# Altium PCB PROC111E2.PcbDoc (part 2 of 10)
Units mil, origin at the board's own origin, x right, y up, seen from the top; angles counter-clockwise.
Board outline 7700 x 2300 mil, 6 copper layers (Top Layer, GND 1, SIG 1, SIG 2, GND 2, Bottom Layer), stack 78.711 mil thick; 767 components, 596 nets, 2755 pads, 1578 vias.
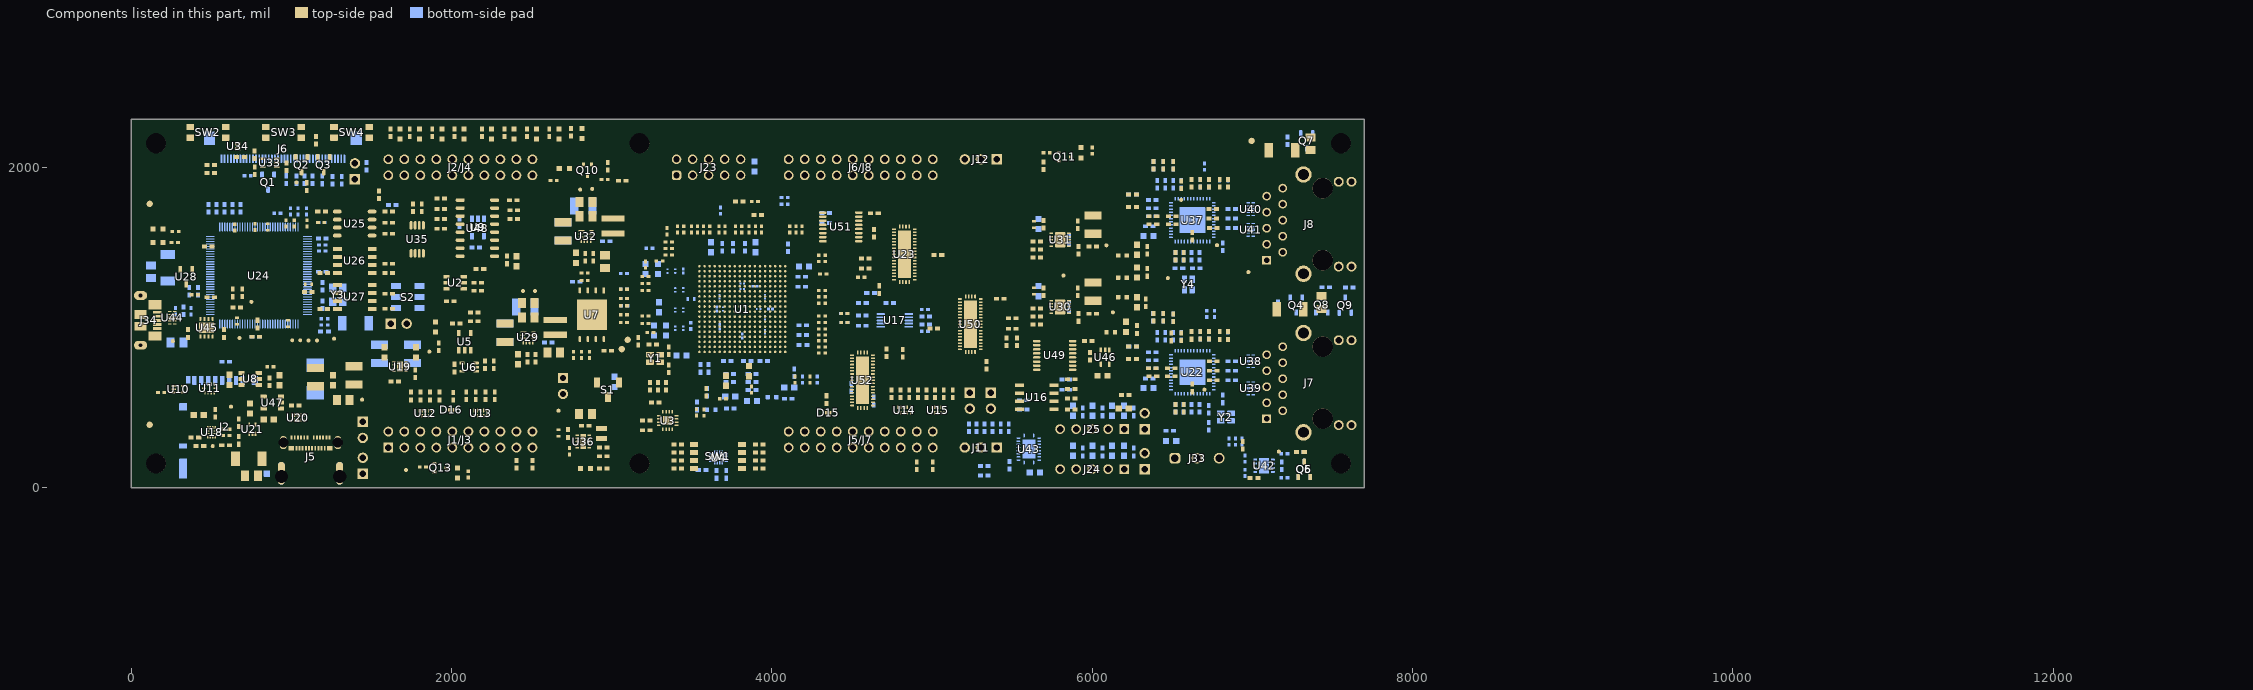
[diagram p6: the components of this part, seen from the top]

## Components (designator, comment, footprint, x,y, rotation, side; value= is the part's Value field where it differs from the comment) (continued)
R129 "ERJ-2GE0R00X" 0402 480.5,1744.01 r270 bottom value=0
R130 "ERJ-2GE0R00X" 0402L 1205.5,1054.21 r180 bottom value=0
R131 "ERJ-2GE0R00X" 0402 530.5,1744.01 r270 bottom value=0
R132 "ERJ-2GEJ101X" 0402L 1205.5,1014.22 r0 bottom value=100
R133 "CRCW040233R2FKED" 0402 580.5,1744.01 r270 bottom value=33.2
R134 "CRCW040233R2FKED" 0402 630.5,1744.01 r270 bottom value=33.2
R135 "CRCW040233R2FKED" 0402 680.5,1744.01 r270 bottom value=33.2
R136 "CRCW0402330KFKED" 0402L 275.17,1101.38 r90 bottom value=330k
R137 "CRCW0402330KFKED" 0402L 371.47,1101.38 r270 bottom value=330k
R138 "CRCW04021K00FKED" 0402L 1187.62,1656.39 r0 bottom value=1.00k
R139 "CRCW04021K00FKED" 0402L 1093.35,1724.68 r90 bottom value=1.00k
R140 "CRCW04021K00FKED" 0402L 1039.13,1724.68 r90 bottom value=1.00k
R141 "CRCW04021K00FKED" 0402L 992.24,1724.68 r90 bottom value=1.00k
R142 "CRCW040249R9FKED" 0402L 1191.36,1514.93 r0 bottom value=49.9
R143 "CRCW040210K0FKED" 0402L 1191.36,1476.93 r0 bottom value=10.0k
R144 "CRCW04021K00FKED" 0402L 395.32,1204.12 r180 top value=1.00k
R145 "CRCW04024K87FKED" 0402L 911.79,1713.62 r0 bottom value=4.87k
R146 "ERJ-2RKF1002X" 0402 2602.33,906.68 r0 bottom value=10.0k
R147 "ERJ-2RKF1002X" 0402 5654.13,1117.63 r180 top value=10.0k
R148 "ERJ-6ENF1822V" 0805_HV 2637.33,844.68 r180 top value=18.2k
R149 "ERJ-2GE0R00X" 0402 5654.13,1017.63 r0 top value=0
R150 "ERJ-2GE0R00X" 0402 5654.13,1067.63 r0 top value=0
R151 "CRCW04023K57FKED" 0402 6004.13,1085.98 r0 top value=3.57k
R152 "CRCW04021K69FKED" 0402 5914.13,1062.36 r90 top value=1.69k
R153 "CRCW04022K49FKED" 0402 2522.33,806.68 r270 top value=2.49k
R154 "CRCW04024K99FKED" 0402 2472.33,806.68 r90 top value=4.99k
R155 "ERJ-2RKF1002X" 0402 5654.13,1536.82 r180 top value=10.0k
R156 "ERJ-2RKF1002X" 0402 2965.12,1537.88 r0 bottom value=10.0k
R157 "ERJ-2GE0R00X" 0402 5654.13,1436.82 r0 top value=0
R158 "ERJ-2GE0R00X" 0402 5654.13,1486.82 r0 top value=0
R159 "CRCW04021K87FKED" 0402 6004.13,1505.17 r0 top value=1.87k
R160 "ERJ-6ENF1822V" 0805_HV 2956.47,1410.85 r90 top value=18.2k
R161 "CRCW04024K99FKED" 0402 5914.13,1481.55 r90 top value=4.99k
R162 "CRCW040215K4FKED" 0402 2884,1439.3 r270 top value=15.4k
R163 "CRCW04024K99FKED" 0402 2834,1439.3 r90 top value=4.99k
R164 "ERJ-2GE0R00X" 0402L 3707,1612.48 r270 top value=0
R165 "ERJ-2GE0R00X" 0402L 3492.19,1009.41 r90 bottom value=0
R166 "ERJ-2GE0R00X" 0402L 3773,1612.48 r270 top value=0
R167 "ERJ-2GE0R00X" 0402L 3209.68,1024.38 r0 top value=0
R168 "ERJ-2GE0R00X" 0402L 3209.68,1072.38 r0 top value=0
R169 "ERJ-2GE0R00X" 0402L 3935,1612.48 r270 top value=0
R170 "ERJ-2GE0R00X" 0402L 3893.31,1786.65 r0 top value=0
R171 "ERJ-2GE0R00X" 0402L 3897,1612.48 r270 top value=0
R172 "ERJ-2GE0R00X" 0402L 3857,1612.48 r270 top value=0
R173 "ERJ-2RKF1002X" 0402 3910.59,1702.62 r180 top value=10.0k
R174 "ERJ-2RKF1002X" 0402 3795.44,1786.65 r180 top value=10.0k
R175 "CRCW04024K70JNED" 0402 4903.31,136.03 r270 top value=4.7k
R176 "CRCW04024K70JNED" 0402 5004.17,136.03 r270 top value=4.7k
R177 "ERJ-2RKF1002X" 0402 966.87,1923.62 r270 bottom value=10.0k
R178 "ERJ-2RKF1002X" 0402 968.08,2004.52 r270 top value=10.0k
R179 "ERJ-2RKF1002X" 0402 769.09,2077.36 r90 top value=10.0k
R180 "ERJ-2GE0R00X" 0402L 725.69,1947.32 r180 bottom value=0
R181 "ERJ-2RKF1002X" 0402 1151.5,2170 r90 top value=10.0k
R182 "ERJ-2RKF1002X" 0402 1255,1920 r90 bottom value=10.0k
R183 "ERJ-2RKF1002X" 0402 1627.39,1765 r180 bottom value=10.0k
R184 "ERJ-2RKF1002X" 0402 1094.86,1880 r90 top value=10.0k
R185 "ERJ-2RKF1002X" 0402 1190.9,1920.91 r90 bottom value=10.0k
R186 "ERJ-2RKF1002X" 0402 1129.84,1921.38 r90 bottom value=10.0k
R187 "ERJ-2RKF1002X" 0402 1079.84,1921.38 r90 bottom value=10.0k
R188 "ERJ-2RKF1002X" 0402 1029.84,1921.38 r90 bottom value=10.0k
R189 "CRCW04024K70JNED" 0402 1468,2007 r90 bottom value=4.7k
R190 "CRCW04024K70JNED" 0402 1813.28,1748.34 r90 top value=4.7k
R191 "CRCW04024K70JNED" 0402 1312.52,1920 r270 bottom value=4.7k
R192 "CRCW04024K70JNED" 0402 1758.28,1748.34 r90 top value=4.7k
R193 "ERJ-2GE0R00X" 0402L 2735,226.63 r270 top value=0
R194 "ERJ-2RKF1002X" 0402 2945,250.25 r0 top value=10.0k
R195 "ERJ-2RKF1003X" 0402 2945,195.25 r0 top value=100k
R196 "ERJ-2GE0R00X" 0402 6375.51,1695.04 r0 bottom value=0
R197 "ERJ-2GE0R00X" 0402 6506.28,1895 r270 bottom value=0
R198 "ERJ-2GE0R00X" 0402 6375.51,1745.04 r0 bottom value=0
R199 "ERJ-2GE0R00X" 0402 6375.51,1795.04 r0 bottom value=0
R200 "ERJ-2GE0R00X" 0402 6406.28,1895 r270 bottom value=0
R201 "ERJ-2GE0R00X" 0402 6456.28,1895 r270 bottom value=0
R202 "ERJ-2RKF1152X" 0402 6815,1503.37 r90 bottom value=11.5k
R203 "CRCW04022K49FKED" 0402 6251.38,1752.65 r180 top value=2.49k
R204 "CRCW04022K49FKED" 0402 6251.38,1830.96 r180 top value=2.49k
R205 "CRCW04022K49FKED" 0402 6506.28,2013.05 r90 top value=2.49k
R206 "CRCW04022K49FKED" 0402 6796.28,1899.68 r90 top value=2.49k
R207 "CRCW04022K49FKED" 0402 6674.39,1900.08 r90 top value=2.49k
R208 "CRCW04022K49FKED" 0402 6729.39,1900.08 r90 top value=2.49k
R209 "CRCW04022K49FKED" 0402 6520,1445 r270 top value=2.49k
R210 "CRCW04022K49FKED" 0402 6383.01,2012.97 r90 top value=2.49k
R211 "CRCW04022K49FKED" 0402 6443.01,2012.97 r90 top value=2.49k
R212 "ERJ-2GE0R00X" 0402 6570,1445 r90 bottom value=0
R213 "ERJ-2GE0R00X" 0402 6520,1445 r90 bottom value=0
R214 "ERJ-2GE0R00X" 0402 6620,1445 r90 bottom value=0
R215 "CRCW04022K49FKED" 0402 6251.3,1752.65 r0 bottom value=2.49k
R216 "CRCW04022K49FKED" 0402 6251.38,1830.96 r0 bottom value=2.49k
R217 "CRCW04022K49FKED" 0402 6506.28,2013.05 r270 bottom value=2.49k
R218 "CRCW04022K49FKED" 0402 6848,1899.68 r270 top value=2.49k
R219 "CRCW04022K49FKED" 0402 6674.39,1900.08 r270 bottom value=2.49k
R220 "CRCW04022K49FKED" 0402 6729.39,1900.08 r270 bottom value=2.49k
R221 "CRCW04022K49FKED" 0402 6570.97,1444.88 r90 top value=2.49k
R222 "CRCW04022K49FKED" 0402 6383.01,2012.97 r270 bottom value=2.49k
R223 "CRCW04022K49FKED" 0402 6443.01,2012.97 r270 bottom value=2.49k
R224 "CRCW0402220RJNED" 0402 7160.2,1135 r270 bottom value=220
R225 "ERJ-2GE0R00X" 0402L 6715,1084.62 r270 bottom value=0
R226 "CRCW0402220RJNED" 0402 7300.38,221.46 r180 top value=220
R227 "ERJ-2GE0R00X" 0402L 6762.73,1085 r270 bottom value=0
R228 "CRCW0402220RJNED" 0402 7300.38,221.46 r180 bottom value=220
R229 "ERJ-2GE0R00X" 0402L 6846.59,947.67 r270 bottom value=0
R230 "CRCW0402220RJNED" 0402 7220,2165 r270 bottom value=220
R231 "ERJ-2GE0R00X" 0402L 6700,2004.69 r270 bottom value=0
R232 "CRCW0402220RJNED" 0402 7457.49,1251.28 r0 bottom value=220
R233 "ERJ-2GE0R00X" 0402L 6795,1896.38 r270 bottom value=0
R234 "CRCW0402220RJNED" 0402 7603.95,1250 r0 bottom value=220
R235 "ERJ-2GE0R00X" 0402L 6848,1896.38 r270 bottom value=0
R236 "ERJ-2RKF4992X" 0402 6259.18,222.12 r90 bottom value=49.9k
R237 "ERJ-2RKF4992X" 0402 6064.18,222.13 r90 bottom value=49.9k
R238 "ERJ-2RKF4992X" 0402 5940,222.13 r90 bottom value=49.9k
R239 "ERJ-2RKF4992X" 0402 6259.18,472.12 r90 bottom value=49.9k
R240 "ERJ-2RKF4992X" 0402 6064.18,472.13 r90 bottom value=49.9k
R241 "ERJ-2RKF4992X" 0402 5940,472.13 r90 bottom value=49.9k
R242 "ERJ-2RKF4992X" 0402 6485.13,355.53 r0 bottom value=49.9k
R243 "ERJ-2RKF4992X" 0402 6205,578.2 r180 top value=49.9k
R244 "CRCW040210K0FKED" 0402L 6935,287.55 r90 bottom value=10.0k
R245 "ERJ-2GE0R00X" 0402L 7200,211.46 r180 bottom value=0
R246 "CRCW040261R9FKED" 0402L 6952.8,91.77 r90 bottom value=61.9
R247 "CRCW040261R9FKED" 0402L 6952.8,181.14 r270 bottom value=61.9
R248 "ERJ-2GE0R00X" 0402L 6855,287.55 r90 bottom value=0
R249 "ERJ-2GE0R00X" 0402L 7200,61.46 r180 bottom value=0
R250 "CRCW040210K0FKED" 0402L 6895,287.55 r270 bottom value=10.0k
R251 "CRCW040251K1FKED" 0402 631.97,1215.23 r90 top value=51.1k
R252 "CRCW040230K0FKED" 0402 691.97,1217.17 r270 top value=30.0k
R253 "ERJ-6ENF1004V" 0805_HV 122.89,1348.06 r90 bottom value=1.00Meg
R254 "ERJ-6ENF1004V" 0805_HV 7430.57,1155 r90 top value=1.00Meg
R255 "ERJ-6ENF1004V" 0805_HV 7364.16,2146.97 r90 top value=1.00Meg
R256 "ERJ-2GEJ102X" 0402 4816.77,838.02 r90 top value=1.0k
R257 "ERJ-2RKF5100X" 0402 1918.27,879.01 r270 top value=510
R258 "ERJ-2RKF1002X" 0402 2974.53,2005.57 r90 top value=10.0k
R259 "ERJ-2GEJ361X" 0402L 270,1530 r0 top value=360
R260 "ERJ-2GEJ361X" 0402L 275,1600 r0 top value=360
R261 "CRCW04021K00FKED" 0402L 965,1650 r270 top value=1.00k
R262 "ERJ-2RKF2200X" 0402 2609.29,2216.18 r270 top value=220
R263 "ERJ-2RKF2200X" 0402 2469.29,2216.18 r270 top value=220
R264 "ERJ-2RKF2200X" 0402 2329.29,2216.18 r270 top value=220
R265 "ERJ-2GEJ361X" 0402L 2636.09,1917.12 r180 top value=360
R266 "ERJ-2RKF2200X" 0402 2189.29,2216.18 r270 top value=220
R267 "ERJ-2RKF2200X" 0402 2017.87,2216.18 r270 top value=220
R268 "ERJ-2RKF1002X" 0402 3065,1915.46 r0 top value=10.0k
R269 "ERJ-2RKF1002X" 0402 2388.01,1731.55 r180 top value=10.0k
R270 "ERJ-2RKF1002X" 0402 1930.93,1676.88 r0 top value=10.0k
R271 "ERJ-2RKF1002X" 0402 1930.93,1804.54 r0 top value=10.0k
R272 "ERJ-2GEJ511X" 0402L 2955,1923.35 r180 top value=510
R273 "ERJ-2RKF2200X" 0402 1877.87,2216.18 r270 top value=220
R274 "ERJ-2RKF1002X" 0402 1930.93,1739.85 r0 top value=10.0k
R275 "ERJ-2RKF1002X" 0402 2388.01,1676.55 r180 top value=10.0k
R276 "ERJ-2RKF1002X" 0402 1930.93,1616.57 r0 top value=10.0k
R277 "ERJ-2RKF2200X" 0402 1737.87,2216.18 r270 top value=220
R278 "ERJ-2GEJ102X" 0402 2385,1795 r180 top value=1.0k
R279 "ERJ-2RKF2200X" 0402 1617.87,2216.18 r270 top value=220
R280 "ERJ-2GE0R00X" 0402L 3074.77,1031.94 r0 top value=0
R281 "ERJ-2GE0R00X" 0402L 3075,1239.6 r0 bottom value=0
R282 "ERJ-2GE0R00X" 0402L 4143,674.68 r90 top value=0
R283 "ERJ-2GE0R00X" 0402L 4190,674.68 r90 bottom value=0
R284 "ERJ-2GE0R00X" 0402L 4282.93,674.68 r90 bottom value=0
R285 "ERJ-2GE0R00X" 0402L 4236.47,674.68 r90 top value=0
R286 "ERJ-2GE0R00X" 0402L 4312.25,1231.79 r180 top value=0
R287 "ERJ-2RKF1002X" 0402 5530,911.55 r90 top value=10.0k
R288 "ERJ-2RKF1002X" 0402 4581.73,1430.9 r0 top value=10.0k
R289 "ERJ-2GEJ102X" 0402 5465.31,911.55 r90 top value=1.0k
R290 "ERJ-2GEJ102X" 0402 4581.73,1367.93 r0 top value=1.0k
R291 "ERJ-2RKF1002X" 0402 4565,1152.36 r0 bottom value=10.0k
R292 "ERJ-2RKF1002X" 0402 5501.38,1057.02 r180 top value=10.0k
R293 "ERJ-2GEJ102X" 0402 4615.26,1215.33 r180 bottom value=1.0k
R294 "ERJ-2GEJ102X" 0402 5501.38,992.02 r180 top value=1.0k
R295 "ERJ-2RKF1002X" 0402 1990,1163.59 r0 top value=10.0k
R296 "ERJ-2RKF1002X" 0402 2176.41,1365 r0 top value=10.0k
R297 "ERJ-2GE0R00X" 0402L 3811,1612.92 r270 top value=0
R298 "ERJ-2RKF1002X" 0402 4336.51,1715.49 r180 bottom value=10.0k
R299 "ERJ-2RKF1002X" 0402 1023.5,512.5 r0 top value=10.0k
R300 "ERJ-2GEJ102X" 0402 4336.51,1652.52 r180 bottom value=1.0k
R302 "ERJ-2GEJ361X" 0402L 6000,2104.27 r270 top value=360
R303 "ERJ-2GEJ511X" 0402L 5715,2090.86 r0 top value=510
R304 "ERJ-2GEJ102X" 0402 5695.31,2008.64 r90 top value=1.0k
R305 "ERJ-2RKF1002X" 0402 6620,950 r270 top value=10.0k
R306 "ERJ-2RKF1002X" 0402 6620,1900.08 r270 top value=10.0k
R307 "ERJ-2GE0R00X" 0402L 3693.94,555 r0 top value=0
R308 "CRCW04021K00FKED" 0402L 1016.99,1650 r270 top value=1.00k
R309 "CRCW04021K00FKED" 0402L 1095.89,1650 r270 top value=1.00k
R310 "CRCW04021K00FKED" 0402L 1184.6,1656.39 r0 top value=1.00k
R311 "CRCW04021K00FKED" 0402L 645,1625 r270 top value=1.00k
R312 "CRCW04021K00FKED" 0402L 772.07,1627.63 r270 top value=1.00k
R313 "CRCW0402130RFKED" 0402 2745.47,2220.12 r270 top value=130
R314 "ERJ-2GEJ361X" 0402L 2103.52,81.9 r90 top value=360
R315 "CRCW0402130RFKED" 0402 2945,120 r0 top value=130
R316 "ERJ-2RKF1002X" 0402 5570,545.04 r0 bottom value=10.0k
R317 "ERJ-2GEJ511X" 0402L 1819.99,127.49 r0 top value=510
R318 "ERJ-2RKF1002X" 0402 5868.93,488.21 r180 top value=10.0k
R319 "ERJ-2RKF1002X" 0402 5835.31,675 r180 bottom value=10.0k
R320 "ERJ-2RKF1002X" 0402 5868.93,676.73 r180 top value=10.0k
R321 "ERJ-2RKF1002X" 0402 5868.93,556.99 r180 top value=10.0k
R322 "ERJ-2RKF1002X" 0402 5835.31,611.02 r180 bottom value=10.0k
R323 "ERJ-2RKF1002X" 0402 5868.93,615 r180 top value=10.0k
R324 "CRCW040233R2FKED" 0402 1607.87,1653.35 r180 top value=33.2
R325 "CRCW040233R2FKED" 0402 1607.87,1584.92 r180 top value=33.2
R326 "CRCW040233R2FKED" 0402 1607.87,1398.01 r180 top value=33.2
R327 "CRCW040233R2FKED" 0402 1607.87,1210 r180 top value=33.2
R328 "CRCW040233R2FKED" 0402 5325,75 r0 bottom value=33.2
R329 "CRCW040233R2FKED" 0402 5325,135.09 r0 bottom value=33.2
R330 "CRCW040233R2FKED" 0402 5229.44,373.51 r270 bottom value=33.2
R331 "CRCW040233R2FKED" 0402 5277.45,373.51 r270 bottom value=33.2
R332 "CRCW040233R2FKED" 0402 5327.45,373.51 r270 bottom value=33.2
R333 "CRCW040233R2FKED" 0402 5377.45,373.51 r270 bottom value=33.2
R334 "CRCW040233R2FKED" 0402 5428.06,373.51 r270 bottom value=33.2
R335 "CRCW040233R2FKED" 0402 5478.01,373.51 r270 bottom value=33.2
S1 "CAS-120TA" SW_CAS-120TA 2975.61,610.94 r270 top
S2 "CAS-D20TA" SW_CAS-D20TA 1724.71,1190 r180 bottom
SH-J1 "60900213421" Wurth_60900213421 12985,2675 r90 top
SH-J2 "60900213421" Wurth_60900213421 9590,2508.18 r90 top
SH-J3 "60900213421" Wurth_60900213421 9590,2146.97 r90 top
SH-J4 "60900213421" Wurth_60900213421 1850.31,-280 r180 top
SH-J5 "60900213421" Wurth_60900213421 1875,-160 r180 top
SH-J6 "60900213421" Wurth_60900213421 4355,-120 r180 top
SH-J7 "60900213421" Wurth_60900213421 4345,-250 r180 top
SW1 "416131160804" FP-416131160804_SMT_SW-MFG 3662.3,194.51 r90 top
SW2 "434351045816" FP-434351045816_SMT_SW_4MM7_4MM5-MFG 477.56,2218.82 r180 top
SW3 "434351045816" FP-434351045816_SMT_SW_4MM7_4MM5-MFG 950,2218.82 r180 top
SW4 "434351045816" FP-434351045816_SMT_SW_4MM7_4MM5-MFG 1375,2218.82 r180 top
TP1 "TP_SM_1MM" TP_SM_1MM 3098.87,922.75 r90 top
TP2 "TP_SM_1MM" TP_SM_1MM 3061.79,864.43 r90 top
TP3 "TESTPOINT" TP_25MIL-SMT 621.55,505.45 r90 top
TP4 "TESTPOINT" TP_25MIL-SMT 1440,548.85 r180 top
TP5 "TESTPOINT" TP_25MIL-SMT 507.51,259.31 r90 top
TP6 "TESTPOINT" TP_25MIL-SMT 2666.85,480 r90 top
TP7 "TESTPOINT" TP_25MIL-SMT 6700.57,611.5 r180 top
TP8 "TESTPOINT" TP_25MIL-SMT 1860,848.96 r90 top
TP9 "TESTPOINT" TP_25MIL-SMT 2877.25,1865 r90 top
TP10 "TESTPOINT" TP_25MIL-SMT 2520,1228.07 r90 top
TP11 "TESTPOINT" TP_25MIL-SMT 6088.14,1513.04 r90 top
TP12 "TESTPOINT" TP_25MIL-SMT 6128.41,1094.72 r90 top
TP13 "TESTPOINT" TP_25MIL-SMT 1715,110 r90 top
TP14 "TESTPOINT" TP_25MIL-SMT 2802.41,1860.51 r90 top
TP15 "TESTPOINT" TP_25MIL-SMT 2445,1228.07 r90 top
TP16 "TESTPOINT" TP_25MIL-SMT 6471.65,1308.13 r90 top
TP17 "TESTPOINT" TP_25MIL-SMT 5820,1323.71 r90 top
TP18 "TESTPOINT" TP_25MIL-SMT 1030,1905 r90 top
TP19 "TESTPOINT" TP_25MIL-SMT 6779.03,1513.91 r0 top
TP20 "TESTPOINT" TP_25MIL-SMT 6555,1797.09 r270 top
TP21 "TESTPOINT" TP_25MIL-SMT 6975,1345.45 r90 top
TP22 "TESTPOINT" TP_25MIL-SMT 7165,225 r90 top
TP23 "TESTPOINT" TP_25MIL-SMT 258.56,915 r0 top
TP24 "TESTPOINT" TP_25MIL-SMT 748.48,1160.35 r0 top
TP25 "TESTPOINT" TP_25MIL-SMT 674.75,934.53 r270 top
TP26 "TESTPOINT" TP_25MIL-SMT 1265,929.89 r0 top
TP27 "TESTPOINT" TP_25MIL-SMT 1003.9,920 r270 top
TP28 "TESTPOINT" TP_25MIL-SMT 1053.9,920 r270 top
TP29 "TESTPOINT" TP_25MIL-SMT 1105.9,919 r270 top
TP30 "TESTPOINT" TP_25MIL-SMT 1158.9,919 r270 top
U1 "AM263x_0p96" "ZCZ (S-PBGA-N324)" 3547.13,1382.8 r0 top locked
U2 "SN74LVC1G11DBVR" DBV0006A_N 2021.24,1279.45 r0 top
U3 "TCA6408ARGTR" RGT0016A 3348.05,418.7 r90 top
U4 "SN74AVC4T245RSVR" RSV0016A 3666.07,187.78 r90 bottom
U5 "SN74LVC1G08DBVR" DBV0005A_N 2081.31,911.4 r90 top
U6 "SN74LVC1G17DCKR" DCK0005A_N 2108.67,752.39 r180 top
U7 "S25FL128SAGNFI000" FP-S25FL128SAGNFI000_WSON8-IPC_B 2875,1079.5 r270 top locked
U8 "TPS22918TDBVTQ1" DBV0006A_N 741.03,678.6 r180 top
U9 "SN74LVC1G08DBVR" DBV0005A_N 2163.97,1624.3 r270 bottom
U10 "TPD2E001DRLR" DRL0005A 292.78,614.21 r0 top
U11 "TPD6E001RSER" RSE0010A 488.2,620 r270 top
U12 "TPD4E02B04DQAR" DQA0010A#1 1835,464.48 r90 top
U13 "TPD4E02B04DQAR" DQA0010A#1 2180,465 r90 top
U14 "TPD4E02B04DQAR" DQA0010A#1 4825,484.12 r90 top
U15 "TPD4E02B04DQAR" DQA0010A#1 5035.4,484.26 r90 top
U16 "CAT24M01WI-GT3" SOIC-8 5652.8,564.14 r180 top
U17 "TS5A23159DGSR" DGS0010A_N 4767.68,1043.75 r0 bottom
U18 "TUSB320LIRWBR" RWB0012A 500.2,345.08 r0 top
U19 "TPS22965TDSGRQ1" DSG0008B 1676.92,755.91 r0 top
U20 "TPD4E02B04DQAR" DQA0010A#1 1038.54,436.99 r270 top
U21 "SN74AHC1G02DRLR" DRL0005A 755.3,365 r90 top
U22 "DP83869HMRGZT" RGZ0048B-MFG 6625.18,720.04 r180 bottom
U23 "TS3DDR3812RUAR" RUA0042A-MFG 4827.2,1456.5 r0 top
U24 "TM4C1294NCPDTT3" PDT0128A 795.5,1324.37 r0 bottom locked
U25 "ISO7220CDR" D0008B_N 1393.86,1648.86 r0 top
U26 "ISO7721DR" D0008B_HV 1395,1415 r180 top
U27 "ISO7721DR" D0008B_HV 1395,1190.27 r180 top
U28 "LM4040C25QDBZR" DBZ0003A_N 341.5,1316.65 r270 top
U29 "TPS62913RPUR" RPU0010A-MFG 2475.89,941.68 r180 top
U30 "TPS74801DRCR" DRC0010J 5799.13,1128.43 r0 top
U31 "TPS74801DRCR" DRC0010J 5799.13,1547.62 r0 top
U32 "TPS62913RPUR" RPU0010A-MFG 2837.56,1574.3 r180 top
U33 "SN74LVC1G07DCKT" DCK0005A_N 863.37,2028.15 r180 top
U34 "SN74LVC2G17DSF2" DSF0006A 665,2131.22 r270 top
U35 "TCA9617BDGKR" DGK0008A_N 1784.37,1550 r90 top
U36 "TPS62177DQCR" DQC0010A 2821.22,287.66 r0 top
U37 "DP83869HMRGZT" RGZ0048B-MFG 6625.18,1670.04 r180 bottom
U38 "TPD4E05U06DQAR" DQA0010A#2 6989.58,788.94 r180 bottom
U39 "TPD4E05U06DQAR" DQA0010A#2 6989.31,619.6 r180 bottom
U40 "TPD4E05U06DQAR" DQA0010A#2 6989.58,1738.94 r180 bottom
U41 "TPD4E05U06DQAR" DQA0010A#2 6989.31,1609.6 r180 bottom
U42 "TCAN1044VDRBTQ1" DRB0008J 7072.8,136.46 r180 bottom
U43 "TXB0108RGYR" RGY0020A 5603.66,240.62 r0 bottom
U44 "TPD4E02B04DQAR" DQA0010A#1 255,1060.81 r180 top
U45 "TPS79601DRBR" DRB0008B 468.69,998.32 r90 top
U46 "SN74LVC1G04DCKR" DCK0005A_N 6080,815 r270 top
U47 "SN74LVC1G08DBVR" DBV0005A_N 879.5,531 r180 top
U48 "TPIC2810D" D0016A_N 2160,1620 r180 top locked
U49 "SN74CB3Q3257PWR" PW0016A_L 5765,825.23 r0 top
U50 "TS3DDR3812RUAR" RUA0042A-MFG 5238.39,1020.04 r180 top
U51 "SN74CB3Q3257PWR" PW0016A_L 4430,1627.91 r0 top
U52 "TS3DDR3812RUAR" RUA0042A-MFG 4565,670 r180 top
Y1 "ABM10W-25.0000MHZ-4-D1X-T3" Abracon_ABM10W 3270,806.21 r90 top
Y2 "ABM10W-25.0000MHZ-4-D1X-T3" Abracon_ABM10W 6834.6,440.5 r90 bottom
Y3 "NX3225GA-16.000M-STD-CRG-1" NDK_NX3225GA 1287.13,1204.32 r180 bottom
Y4 "ABM10W-25.0000MHZ-4-D1X-T3" Abracon_ABM10W 6600,1268.41 r0 bottom
ZZ1 "This Assembly Note is for PCB labels only" AssemblyNoteLabel 100,7500 r0 top
ZZ2 "These assemblies are ESD sensitive, ESD precautions shall be observed." AssemblyNote 100,7400 r0 top
ZZ3 "These assemblies must be clean and free from flux and all contaminants. Use of no clean flux is not acceptable." AssemblyNote 100,7300 r0 top
ZZ4 "These assemblies must comply with workmanship standards IPC-A-610 Class 2, unless otherwise specified." AssemblyNote 100,7200 r0 top
? "Comment" MISTRAL_LOGO_25 6689.32,1155.04 r0 top
? "Comment" MHNP_M3_PANHEAD_PHILLIPS 3173.18,150 r0 top
? "Comment" MHNP_M3_PANHEAD_PHILLIPS 7554.17,150 r0 top
? "Comment" MHNP_M3_PANHEAD_PHILLIPS 7554.17,2150 r0 top locked
? "Comment" MHNP_M3_PANHEAD_PHILLIPS 3173.18,2150 r0 top locked
? "Comment" MHNP_M3_PANHEAD_PHILLIPS 154.17,2150 r0 top
? "Comment" MHNP_M3_PANHEAD_PHILLIPS 154.17,150 r0 top locked

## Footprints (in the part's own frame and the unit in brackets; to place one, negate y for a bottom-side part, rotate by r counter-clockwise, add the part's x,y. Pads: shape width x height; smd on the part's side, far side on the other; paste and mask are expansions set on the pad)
0201 [mm] "Data from Kemet datasheet CC101_COM dated 7/28/11"
  rect 0.46x0.42 smd mask+0.048: 1(-0.33,0) 2(0.33,0)
  body extent -0.31,-0.16 0.31,0.16, height 0.26
0402 [mm] "0402 from SM-752 data"
  rect 0.8x0.6 smd: 1(-0.6,0) 2(0.6,0)
  silkscreen extent -1.22,-0.52 1.22,0.52, body extent -0.55,-0.3 0.55,0.3, height 0.6
0402_070 [mil] "SMD, 2-Leads, Body 1.2x0.7mm, Height 0.7mm"
  rect 15x24 smd: 1(-20,0) 2(20,0)
  body extent -24,-14 24,14, height 28
0402L [mm] "0402 from SM-752 data"
  rect 0.6x0.5 smd: 1(-0.5,0) 2(0.5,0)
  body extent -0.55,-0.3 0.55,0.3, height 0.6
0402S [mil] "Based on C0402S footprint from PADS legacy"
  rect 15x24 smd: 1(-20,0) 2(20,0)
  body extent -22,-12 22,12, height 24
0603 [mm] "0603 from SM-752 data"
  rect 1x0.95 smd: 1(-0.8,0) 2(0.8,0)
  silkscreen extent -1.52,-0.69 1.52,0.69, body extent -0.87,-0.47 0.87,0.47, height 1
0805_HV [mil] "0805 with 30mil clearance between pads"
  rect 50x63 smd: 1(-40,0) 2(40,0)
  silkscreen extent -74,-40 74,40, body extent -43,-29 43,29, height 57
1210_270 [mm] "1210"
  rect 1.3x2.7 smd: 1(-1.45,0) 2(1.45,0)
  silkscreen extent -2.32,-1.57 2.32,1.57, body extent -1.7,-1.35 1.7,1.35, height 2.7
1808 [mm] "Chip Capacitor, Body 4.6x2.0mm, IPC Medium Density"
  rect 1.4x2.3 smd: 1(-2.1,0) 2(2.1,0)
  silkscreen extent -3.1,-1.45 3.1,1.45, body extent -2.47,-1.2 2.47,1.2, height 2.03
Abracon_ABM10W [mm] "SMD, 4-Leads, Body 2x2.5mm"
  rrect12% 0.85x1.2 smd: 1(-0.6,0.813) 2(-0.6,-0.813) 3(0.6,-0.813) 4(0.6,0.813)
  body extent -1.05,-1.3 1.05,1.3, height 0.6
AssemblyNote [mil] "Assembly Note"
AssemblyNoteLabel [mil] "Assembly Note for PCB Labels"
BoosterPack_40pin_J1J3 [mm] "Receptacle, 2.54mm, 10x2, TH"
  rrect6% 1.55x1.55 hole 1.02: 1(1.27,11.43)
  round 1.55 hole 1.02: 2(1.27,8.89) 3(1.27,6.35) 4(1.27,3.81) 5(1.27,1.27) 6(1.27,-1.27) 7(1.27,-3.81) 8(1.27,-6.35) 9(1.27,-8.89) 10(1.27,-11.43) 21(-1.27,11.43) 22(-1.27,8.89) 23(-1.27,6.35) 24(-1.27,3.81) 25(-1.27,1.27) 26(-1.27,-1.27) 27(-1.27,-3.81) 28(-1.27,-6.35) 29(-1.27,-8.89) 30(-1.27,-11.43)
  silkscreen extent -7.62,-12.95 7.62,12.95, body extent -2.48,-12.95 2.48,12.95, height 8.51
BoosterPack_40pin_J2J4 [mm] "Receptacle, 2.54mm, 10x2, TH"
  round 1.55 hole 1.02: 11(-1.27,-11.43) 12(-1.27,-8.89) 13(-1.27,-6.35) 14(-1.27,-3.81) 15(-1.27,-1.27) 16(-1.27,1.27) 17(-1.27,3.81) 18(-1.27,6.35) 19(-1.27,8.89) 20(-1.27,11.43) 31(1.27,-11.43) 32(1.27,-8.89) 33(1.27,-6.35) 34(1.27,-3.81) 35(1.27,-1.27) 36(1.27,1.27) 37(1.27,3.81) 38(1.27,6.35) 39(1.27,8.89) 40(1.27,11.43)
  silkscreen extent -7.62,-12.95 2.48,12.95, body extent -2.48,-12.95 2.48,12.95, height 8.51
BoosterPack_40pin_J5J7 [mm] "Receptacle, 2.54mm, 10x2, TH"
  round 1.55 hole 1.02: 41(1.27,11.43) 42(1.27,8.89) 43(1.27,6.35) 44(1.27,3.81) 45(1.27,1.27) 46(1.27,-1.27) 47(1.27,-3.81) 48(1.27,-6.35) 49(1.27,-8.89) 50(1.27,-11.43) 61(-1.27,11.43) 62(-1.27,8.89) 63(-1.27,6.35) 64(-1.27,3.81) 65(-1.27,1.27) 66(-1.27,-1.27) 67(-1.27,-3.81) 68(-1.27,-6.35) 69(-1.27,-8.89) 70(-1.27,-11.43)
  silkscreen extent -2.48,-12.95 7.62,12.95, body extent -2.48,-12.95 2.48,12.95, height 8.51
BoosterPack_40pin_J6J8 [mm] "Receptacle, 2.54mm, 10x2, TH"
  round 1.55 hole 1.02: 51(-1.27,-11.43) 52(-1.27,-8.89) 53(-1.27,-6.35) 54(-1.27,-3.81) 55(-1.27,-1.27) 56(-1.27,1.27) 57(-1.27,3.81) 58(-1.27,6.35) 59(-1.27,8.89) 60(-1.27,11.43) 71(1.27,-11.43) 72(1.27,-8.89) 73(1.27,-6.35) 74(1.27,-3.81) 75(1.27,-1.27) 76(1.27,1.27) 77(1.27,3.81) 78(1.27,6.35) 79(1.27,8.89) 80(1.27,11.43)
  silkscreen extent -7.62,-12.95 2.48,12.95, body extent -2.48,-12.95 2.48,12.95, height 8.51
CE_Mark_5mm [mil] "Minimum text height for CE Mark"
  silkscreen extent -138,-98 138,98
D0008B_HV [mm] "SOIC, 8-Leads, Body 4.9x3.9mm, Pitch 1.27mm, HV / Isolation option"
  rrect17% 1.4x0.6 smd: 1(-2.75,1.905) 2(-2.75,0.635) 3(-2.75,-0.635) 4(-2.75,-1.905) 5(2.75,-1.905) 6(2.75,-0.635) 7(2.75,0.635) 8(2.75,1.905)
  silkscreen extent -3.3,-2.5 0.9,2.5, body extent -3,-2.45 3,2.45, height 1.63
D0008B_N [mil] "SOIC, 8-Leads, Body 4.9x3.9mm, Pitch 1.27mm, IPC Medium Density"
  oval 55x23.62 smd: 1(-108.5,75) 2(-108.5,25) 3(-108.5,-25) 4(-108.5,-75) 5(108.5,-75) 6(108.5,-25) 7(108.5,25) 8(108.5,75)
  silkscreen extent -130,-98 35,98, body extent -118,-96 118,96, height 64
D0016A_N [mm] "SOIC, 16-Leads, Body 9.9x3.9mm, Pitch 1.27mm, IPC Medium Density"
  oval 1.45x0.6 smd: 1(-2.725,4.445) 2(-2.725,3.175) 3(-2.725,1.905) 4(-2.725,0.635) 5(-2.725,-0.635) 6(-2.725,-1.905) 7(-2.725,-3.175) 8(-2.725,-4.445) 9(2.725,-4.445) 10(2.725,-3.175) 11(2.725,-1.905) 12(2.725,-0.635) 13(2.725,0.635) 14(2.725,1.905) 15(2.725,3.175) 16(2.725,4.445)
  silkscreen extent -3.3,-5 0.9,5, body extent -3,-4.95 3,4.95, height 1.6
DBV0005A_N [mm] "SOT23, 5-Leads, Body 2.9x1.6mm, Pitch 0.95mm, Lead Span 2.8mm, IPC Medium Density"
  rrect17% 1x0.6 smd: 1(-1.375,0.95) 2(-1.375,0) 3(-1.375,-0.95) 4(1.375,-0.95) 5(1.375,0.95)
  silkscreen extent -0.25,-1.55 0.25,1.55, body extent -1.42,-1.46 1.42,1.46, height 1.09
DBV0006A_N [mm] "SOT23, 6-Leads, Body 2.9x1.6mm, Pitch 0.95mm, Lead Span 2.8mm, IPC Medium Density"
  rrect17% 1x0.6 smd: 1(-1.375,0.95) 2(-1.375,0) 3(-1.375,-0.95) 4(1.375,-0.95) 5(1.375,0) 6(1.375,0.95)
  silkscreen extent -1.68,-1.55 0.5,1.55, body extent -1.42,-1.46 1.42,1.46, height 1.12
DBZ0003A_N [mm] "SOT23, 3-Leads, Body 2.9x1.3mm, Pitch 0.95mm, Lead Span 2.4mm, IPC Medium Density"
  rrect17% 1x0.6 smd: 1(-1.2,0.95) 2(-1.2,-0.95) 3(1.2,0)
  silkscreen extent 0.2,-1.5 0.7,1.5, body extent -1.26,-1.46 1.26,1.46, height 0.98
DCK0005A_N [mm] "SOT353, 5-Leads, Body 2x1.3mm, Pitch 0.65mm, Lead Span 2.1mm, IPC Medium Density"
  rrect25% 0.85x0.4 smd: 1(-1.125,0.65) 2(-1.125,0) 3(-1.125,-0.65) 4(1.125,-0.65) 5(1.125,0.65)
  silkscreen extent -1.48,-1.02 0.55,1.1, body extent -1.14,-1 1.14,1, height 0.95
DGK0008A_N [mm] "TSOP, 8-Leads, Body 3x3mm, Pitch 0.65mm, IPC Medium Density"
  oval 1.35x0.45 smd: 1(-2.225,0.975) 2(-2.225,0.325) 3(-2.225,-0.325) 4(-2.225,-0.975) 5(2.225,-0.975) 6(2.225,-0.325) 7(2.225,0.325) 8(2.225,0.975)
  silkscreen extent -2.75,-1.55 0.95,1.55, body extent -2.45,-1.5 2.45,1.5, height 0.96
DGS0010A_N [mm] "TSSOP, 10-Leads, Body 3x3mm, Pitch 0.5mm, IPC Medium Density"
  oval 1.35x0.3 smd: 1(-2.225,1) 2(-2.225,0.5) 3(-2.225,0) 4(-2.225,-0.5) 5(-2.225,-1) 6(2.225,-1) 7(2.225,-0.5) 8(2.225,0) 9(2.225,0.5) 10(2.225,1)
  silkscreen extent -2.75,-1.55 0.9,1.55, body extent -2.45,-1.5 2.45,1.5, height 0.96
DPY0002A [mm] "X1SON-2"
  rrect57% 0.35x0.6 smd paste-0.5 mask-0.05: 1(-0.325,0) 2(0.325,0)
  rrect50% 0.3x0.5 on Top Paste: 1S(-0.35,0) 2S(0.35,0)
  silkscreen extent -0.85,-0.02 -0.8,0.02, body extent -0.5,-0.3 0.5,0.3, height 0.45
DQA0010A#1 [mm] "SON, 10-Leads, Body 1x2.5mm, Pitch 0.5mm, TI Recommended"
  rrect50% 0.565x0.2 smd: 1(-0.417,1) 2(-0.417,0.5) 4(-0.417,-0.5) 5(-0.417,-1) 6(0.417,-1) 7(0.417,-0.5) 9(0.417,0.5) 10(0.417,1)
  rrect28% 0.565x0.36 on Top Paste: 3(-0.417,0) 8(0.417,0)
  rrect25% 0.565x0.4 smd paste-0.2: 3(-0.417,0) 8(0.417,0)
  silkscreen extent -0.67,-1.45 0.55,1.45, body extent -0.55,-1.3 0.55,1.3, height 0.56
DQA0010A#2 [mm] "SON, 10-Leads, Body 1x2.5mm, Pitch 0.5mm, TI Recommended"
  rrect50% 0.565x0.2 smd: 1(-0.417,1) 2(-0.417,0.5) 4(-0.417,-0.5) 5(-0.417,-1) 6(0.417,-1) 7(0.417,-0.5) 9(0.417,0.5) 10(0.417,1)
  rrect28% 0.565x0.36 on Bottom Paste: 3(-0.417,0) 8(0.417,0)
  rrect25% 0.565x0.4 smd paste-0.2: 3(-0.417,0) 8(0.417,0)
  silkscreen extent -0.67,-1.45 0.55,1.45, body extent -0.55,-1.3 0.55,1.3, height 0.56
DQC0010A [mm] "SON, 10-Leads, Body 2x3mm, Pitch 0.5mm, Thermal Pad 2.4x0.84mm"
  rrect40% 0.5x0.25 smd: 1(-0.95,1) 2(-0.95,0.5) 3(-0.95,0) 4(-0.95,-0.5) 5(-0.95,-1) 6(0.95,-1) 7(0.95,-0.5) 8(0.95,0) 9(0.95,0.5) 10(0.95,1)
  rrect12% 0.8x1.08 on Top Paste: 11(0,-0.64) 11(0,0.64)
  rrect12% 0.84x2.4 smd paste-0.42: 11(0,0)
  silkscreen extent -1.18,-1.68 1.17,1.68, body extent -1,-1.5 1,1.5, height 0.77
DRB0008B [mm] "SON, 8-Leads, Body 3x3mm, Pitch 0.65mm, Thermal Pad 2.4x1.65mm, TI Recommended"
  rrect33% 0.6x0.3 smd: 1(-1.4,0.975) 2(-1.4,0.325) 3(-1.4,-0.325) 4(-1.4,-0.975) 5(1.4,-0.975) 6(1.4,-0.325) 7(1.4,0.325) 8(1.4,0.975)
  rrect50% 1.47x1.06 on Top Paste: 9(0,0.63) 9(0,-0.63)
  rrect6% 1.65x2.4 smd paste-1.2: 9(0,0)
  silkscreen extent -1.73,-1.73 1.73,1.73, body extent -1.5,-1.5 1.5,1.5, height 0.96
DRB0008J [mm] "VSON-8"
  rrect33% 0.6x0.31 smd: 1(-1.4,0.975) 2(-1.4,0.325) 3(-1.4,-0.325) 4(-1.4,-0.975) 5(1.4,-0.975) 6(1.4,-0.325) 7(1.4,0.325) 8(1.4,0.975)
  rrect6% 1.65x2.4 smd paste-1.2: 9(0,0)
  silkscreen extent -1.73,-1.73 1.73,1.73, body extent -1.55,-1.55 1.55,1.55, height 1.01
DRC0010J [mm] "VSON-10"
  rrect42% 0.6x0.24 smd: 1(-1.4,1) 2(-1.4,0.5) 3(-1.4,0) 4(-1.4,-0.5) 5(-1.4,-1) 6(1.4,-1) 7(1.4,-0.5) 8(1.4,0) 9(1.4,0.5) 10(1.4,1)
  rrect12% 1.65x2.4 smd paste-1 mask-2: 11(0,0)
  Top Layer region: -0.375,-1.65 -0.375,-1.2 -0.775,-1.2 -0.794,-1.196 -0.81,-1.185 -0.821,-1.169 -0.825,-1.15 -0.825,-1.15 -0.825,1.15 -0.821,1.169 -0.81,1.185 -0.794,1.196 -0.775,1.2 -0.775,1.2 -0.375,1.2 -0.375,1.65 -0.371,1.669 -0.36,1.685 -0.344,1.696 -0.325,1.7 -0.325,1.7 -0.325,1.7 -0.175,1.7 -0.175,1.7 -0.156,1.696 -0.14,1.685 -0.129,1.669 -0.125,1.65 -0.125,1.65 -0.125,1.2 0.125,1.2 0.125,1.65 0.129,1.669 0.14,1.685 0.156,1.696 0.175,1.7 0.175,1.7 0.175,1.7 0.325,1.7 0.325,1.7 0.344,1.696 0.36,1.685 0.371,1.669 0.375,1.65 0.375,1.65 0.375,1.2 0.775,1.2 0.794,1.196 0.81,1.185 0.821,1.169 0.825,1.15 0.825,1.15 0.825,-1.15 0.821,-1.169 0.81,-1.185 0.794,-1.196 0.775,-1.2 0.775,-1.2 0.375,-1.2 0.375,-1.65 0.371,-1.669 0.36,-1.685 0.344,-1.696 0.325,-1.7 0.325,-1.7 0.175,-1.7 0.156,-1.696 0.14,-1.685 0.129,-1.669 0.125,-1.65 0.125,-1.65 0.125,-1.2 -0.125,-1.2 -0.125,-1.65 -0.129,-1.669 -0.14,-1.685 -0.156,-1.696 -0.175,-1.7 -0.175,-1.7 -0.325,-1.7 -0.344,-1.696 -0.36,-1.685 -0.371,-1.669 -0.375,-1.65
  body extent -1.5,-1.5 1.5,1.5, height 1
DRL0005A [mm] "SOTFL, 5-Flat Leads, Body 1.2x1.6x0.6mm, Pitch 0.5mm, TI recommended"
  rrect33% 0.67x0.3 smd: 1(-0.74,0.5) 2(-0.74,0) 3(-0.74,-0.5) 4(0.74,-0.5) 5(0.74,0.5)
  silkscreen extent -0.9,-0.95 0.5,0.95, body extent -0.85,-0.85 0.85,0.85, height 0.62
DSF0006A [mm] "TI recommended land pattern"
  rrect59% 0.6x0.17 smd mask+0.045: 1(-0.4,0.35) 2(-0.4,0) 3(-0.4,-0.35) 4(0.4,-0.35) 5(0.4,0) 6(0.4,0.35)
  silkscreen extent -0.6,-0.63 0.6,0.63, body extent -0.5,-0.5 0.5,0.5, height 0.48
DSG0008B [mm] "SON, 8-Leads, Body 2x2mm, Pitch 0.5mm, Thermal Pad 1.6x0.9mm, TI Recommended"
  rrect14% 0.9x0.7 on Top Paste: 0(0,-0.45) 0(0,0.45)
  rrect40% 0.5x0.25 smd: 1(-0.95,0.75) 2(-0.95,0.25) 3(-0.95,-0.25) 4(-0.95,-0.75) 5(0.95,-0.75) 6(0.95,-0.25) 7(0.95,0.25) 8(0.95,0.75)
  rrect11% 0.9x1.6 smd paste-0.45: 9(0,0)
  silkscreen extent -1.07,-1.15 1.07,1.15, body extent -1,-1 1,1, height 0.77
FCC_disclaimer [mil]
Fiducial10-20 [mm]
  round 1 smd mask+0.5: 1(0,0)
  Top Layer keep-out circle w1.178: c0,0 r0.5
FP-2012670005_CONN_USB_9MM39_8MM21-MFG [mm]
  rrect100% 1.1x2.1 hole 1.6 slot 0.6 at 0 deg paste-1000 mask+0: 1(-4.32,3.205) 2(4.32,3.205)
  rrect100% 0.6x2.1 hole 2.1 slot 0.6 at 0 deg paste-1000 mask+0: 3(-4.62,-2.155) 4(4.62,-2.155)
  rrect100% 1.1x3.6 smd paste-1000 mask+0: 3(-4.62,-1.655) 4(4.62,-1.655)
  rrect100% 1.1x3.6 smd far side paste-1000 mask+0: 3(-4.62,-1.655) 4(4.62,-1.655)
  rrect33% 0.3x0.7 smd paste+0 mask+0: A1(-3,4.015) A2(-2.5,4.015) A3(-2,4.015) A4(-1.5,4.015) A5(-1,4.015) A6(-0.5,4.015) A7(0.5,4.015) A8(1,4.015) A9(1.5,4.015) A10(2,4.015) A11(2.5,4.015) A12(3,4.015) B2(2.25,2.315) B3(1.75,2.315) B4(1.25,2.315) B5(0.75,2.315) B6(0.25,2.315) B7(-0.25,2.315) B8(-0.75,2.315) B9(-1.25,2.315) B10(-1.75,2.315) B11(-2.25,2.315)
  rrect14% 0.9x0.7 smd paste+0 mask+0: B1(3.05,2.315) B12(-3.05,2.315)
  silkscreen extent -4.77,0.52 4.77,5.03, body extent -5.27,-4.33 5.27,4.46, height 0.25
FP-74405020100_SMT_IND_2MM0_1MM6-MFG [mm]
  rect 0.8x1.7 smd paste+0 mask+0: 1(-0.8,0) 2(0.8,0)
  body extent -1.3,-1 1.3,1, height 0.25
FP-416131160804_SMT_SW-MFG [mm]
  rrect13% 0.76x1.27 smd paste+0 mask+0: 1(-1.905,-3.81) 2(-0.635,-3.81) 3(0.635,-3.81) 4(1.905,-3.81) 5(1.905,3.81) 6(0.635,3.81) 7(-0.635,3.81) 8(-1.905,3.81)
  silkscreen extent -3.27,-4.12 3.27,2.93, body extent -3.37,-4.54 3.37,4.54, height 0.25
FP-434351045816_SMT_SW_4MM7_4MM5-MFG [mm]
  rrect10% 1.2x1 smd paste+0 mask+0: 1(2.8,0.85) 2(2.8,-0.85) 3(-2.8,0.85) 4(-2.8,-0.85)
  silkscreen extent -2.4,0.73 4.07,1.85, body extent -3.5,-2.95 3.5,1.95, height 0.25
FP-BLM18EG121SN1D_0603-MFG [mm]
  rrect15% 0.65x0.7 smd paste+0 mask+0: 1(-0.675,0) 2(0.675,0)
  silkscreen extent -0.87,-0.8 0.87,0.8, body extent -0.8,-0.4 0.8,0.4, height 0.95
FP-FH12A-40S-0.5SH(55)_FFC40-MFG [mm]
  rrect33% 0.3x1.3 smd paste-1000 mask+0: 1(9.75,-3.725) 2(9.25,-3.725) 3(8.75,-3.725) 4(8.25,-3.725) 5(7.75,-3.725) 6(7.25,-3.725) 7(6.75,-3.725) 8(6.25,-3.725) 9(5.75,-3.725) 10(5.25,-3.725) 11(4.75,-3.725) 12(4.25,-3.725) 13(3.75,-3.725) 14(3.25,-3.725) 15(2.75,-3.725) 16(2.25,-3.725) 17(1.75,-3.725) 18(1.25,-3.725) 19(0.75,-3.725) 20(0.25,-3.725) 21(-0.25,-3.725) 22(-0.75,-3.725) 23(-1.25,-3.725) 24(-1.75,-3.725) 25(-2.25,-3.725) 26(-2.75,-3.725) 27(-3.25,-3.725) 28(-3.75,-3.725) 29(-4.25,-3.725) 30(-4.75,-3.725) 31(-5.25,-3.725) 32(-5.75,-3.725) 33(-6.25,-3.725) 34(-6.75,-3.725) 35(-7.25,-3.725) 36(-7.75,-3.725) 37(-8.25,-3.725) 38(-8.75,-3.725) 39(-9.25,-3.725) 40(-9.75,-3.725)
  rrect6% 1.8x2.2 smd paste+0 mask+0: 41(-11.65,-0.475) 42(11.65,-0.475)
  silkscreen extent -12.35,-5.07 12.35,3.2, body extent -12.25,-3.82 12.25,2.95, height 3.5
FP-GRM033C80J105ME05D_0201-MFG [mm]
  rrect33% 0.3x0.35 smd paste+0 mask+0: 1(-0.282,0) 2(0.282,0)
  silkscreen extent -0.35,-0.58 0.35,0.58, body extent -0.3,-0.15 0.3,0.15, height 0.39
FP-LPJG16314A4NL_CONN_RJ45-MFG [mm]
  rrect7% 1.4x1.4 hole 0.9 paste-1000 mask+0: 1(-5.715,9.015)
  round 1.4 hole 0.9 paste-1000 mask+0: 2(-4.445,6.475) 3(-3.175,9.015) 4(-1.905,6.475) 5(-0.635,9.015) 6(0.635,6.475) 7(1.905,9.015) 8(3.175,6.475) 9(4.445,9.015) 10(5.715,6.475)
  round 1.57 hole 1.02 paste-1000 mask+0: 11(6.725,-2.415) 12(6.725,-4.445) 13(-6.725,-2.415) 14(-6.725,-4.445)
  round 2.6 hole 1.7 paste-1000 mask+0: 15(-7.875,3.175) 16(7.875,3.175)
  round 3.25 hole 3.25 unplated paste-1000 mask+0: ""(-5.715,0.125) ""(5.715,0.125)
  silkscreen extent -9.65,-10.75 8.1,10.75, body extent -9.28,-10.85 9.28,10.85, height 0.25
FP-S25FL128SAGNFI000_WSON8-IPC_B [mm]
  rrect25% 0.961x0.392 smd paste+0 mask+0: 1(-3.876,1.905)
  rrect100% 0.961x0.392 smd paste+0 mask+0: 2(-3.876,0.635) 3(-3.876,-0.635) 4(-3.876,-1.905) 5(3.876,-1.905) 6(3.876,-0.635) 7(3.876,0.635) 8(3.876,1.905)
  rrect2% 4.9x4.75 smd paste-1000 mask+0: 9(0,0)
  silkscreen extent -5.03,-3 4,3, body extent -4.61,-3.25 4.61,3.25, height 0.25
Hirose_DM3BT-DSF-PEJS [mm] "Conncetor, micro SD, 8+2 Pos, R/A, SMT"
  rrect14% 0.7x1.4 smd: 1(-3.2,7.8) 2(-2.1,7.8) 3(-1,7.8) 4(0.1,7.8) 5(1.2,7.8) 6(2.3,7.8) 7(3.4,7.8) 8(4.5,7.8)
  rrect8% 1.2x0.8 smd: 9(6.3,-2.6)
  rrect14% 0.7x1.2 smd: 10(5.45,7.9)
  rrect10% 1x1.4 smd: S1(-5.1,7.8)
  rrect8% 1.2x1.2 smd: S2(6.3,3.6)
  rrect8% 1.2x3.2 smd: S3(6.3,-6.2)
  rrect8% 1x1 smd: S4(-7,-7)
  Top Layer region: -7.75,-8.15 -5.75,-8.15 -5.75,-7.65 -6.1,-7.65 -6.25,-7.5 -6.25,-6.25 -7.75,-6.25
  body extent -6.93,-7.98 6.93,7.98, height 2.38
Label_650x200 [mil] "Thermal Transfer Label"
  round 1 on Mech13: 0(0,0)
  silkscreen extent -325,-100 325,100, body extent -325,-100 325,100, height 1
MHNP_M3_PANHEAD_PHILLIPS [mil]
  round 121 hole 126 unplated mask+5.5: ""(0,0)
  Keep-Out Layer circle w1: c0,0 r126
MISTRAL_LOGO_25 [mil]
  silkscreen extent 0,0 297,162
Molex_1051640001 [mm] "Receptacle, USB 2.0, Micro B, 5 Pos, 0.65mm Pitch, R/A, SMT"
  rrect22% 0.45x1.38 smd: 1(1.3,4.11) 2(0.65,4.11) 3(0,4.11) 4(-0.65,4.11) 5(-1.3,4.11)
  rrect7% 1.475x2.1 smd: 6(-2.462,3.75) 11(2.462,3.75)
  rrect100% 1.4x2.1 hole 0.6 slot 1.3 at 90 deg: 7(-3.95,1.45) 10(3.95,1.45)
  rrect7% 1.375x1.9 smd: 8(-0.937,1.45) 9(0.937,1.45)
  silkscreen extent 1.2,5.1 1.4,5.4, body extent -4.1,-0.7 4.1,4.47, height 2.45
NDK_NX3225GA [mm] "NDK"
  rect 1.2x1.4 smd: 1(-0.8,1.1) 2(-0.8,-1.1) 3(0.8,-1.1) 4(0.8,1.1)
  silkscreen extent -1.9,-0.1 1.4,2, body extent -1.3,-1.65 1.3,1.65, height 0.9
On-Shore_OSTTE030161 [mm] "Terminal Block, 3.5mm, 3x1, TH"
  rrect50% 1.7x1.7 hole 1.2: 1(-3.5,0)
  round 1.7 hole 1.2: 2(0,0) 3(3.5,0)
  silkscreen extent -5.25,-3.6 5.25,4.05, body extent -5.75,-3.6 5.75,3.4, height 8.4
PBC03SAAN [mm] "Sullins 100mil, 1x3, 230 mil above insulator"
  rect 1.65x1.65 hole 1.016: 1(-2.54,0)
  round 1.65 hole 1.016: 2(0,0) 3(2.54,0)
  silkscreen extent -3.81,-1.27 3.81,1.27, body extent -3.81,-1.27 3.81,1.27, height 8.38
PDT0128A [mm] "Thin QFP, 128-Leads, Body 14x14mm, Pitch 0.4mm"
  oval 1.4x0.2 smd: 1(-7.7,6.2) 2(-7.7,5.8) 3(-7.7,5.4) 4(-7.7,5) 5(-7.7,4.6) 6(-7.7,4.2) 7(-7.7,3.8) 8(-7.7,3.4) 9(-7.7,3) 10(-7.7,2.6) 11(-7.7,2.2) 12(-7.7,1.8) 13(-7.7,1.4) 14(-7.7,1) 15(-7.7,0.6) 16(-7.7,0.2) 17(-7.7,-0.2) 18(-7.7,-0.6) 19(-7.7,-1) 20(-7.7,-1.4) 21(-7.7,-1.8) 22(-7.7,-2.2) 23(-7.7,-2.6) 24(-7.7,-3) 25(-7.7,-3.4) 26(-7.7,-3.8) 27(-7.7,-4.2) 28(-7.7,-4.6) 29(-7.7,-5) 30(-7.7,-5.4) 31(-7.7,-5.8) 32(-7.7,-6.2) 65(7.7,-6.2) 66(7.7,-5.8) 67(7.7,-5.4) 68(7.7,-5) 69(7.7,-4.6) 70(7.7,-4.2) 71(7.7,-3.8) 72(7.7,-3.4) 73(7.7,-3) 74(7.7,-2.6) 75(7.7,-2.2) 76(7.7,-1.8) 77(7.7,-1.4) 78(7.7,-1) 79(7.7,-0.6) 80(7.7,-0.2) 81(7.7,0.2) 82(7.7,0.6) 83(7.7,1) 84(7.7,1.4) 85(7.7,1.8) 86(7.7,2.2) 87(7.7,2.6) 88(7.7,3) 89(7.7,3.4) 90(7.7,3.8) 91(7.7,4.2) 92(7.7,4.6) 93(7.7,5) 94(7.7,5.4) 95(7.7,5.8) 96(7.7,6.2)
  oval 0.2x1.4 smd: 33(-6.2,-7.7) 34(-5.8,-7.7) 35(-5.4,-7.7) 36(-5,-7.7) 37(-4.6,-7.7) 38(-4.2,-7.7) 39(-3.8,-7.7) 40(-3.4,-7.7) 41(-3,-7.7) 42(-2.6,-7.7) 43(-2.2,-7.7) 44(-1.8,-7.7) 45(-1.4,-7.7) 46(-1,-7.7) 47(-0.6,-7.7) 48(-0.2,-7.7) 49(0.2,-7.7) 50(0.6,-7.7) 51(1,-7.7) 52(1.4,-7.7) 53(1.8,-7.7) 54(2.2,-7.7) 55(2.6,-7.7) 56(3,-7.7) 57(3.4,-7.7) 58(3.8,-7.7) 59(4.2,-7.7) 60(4.6,-7.7) 61(5,-7.7) 62(5.4,-7.7) 63(5.8,-7.7) 64(6.2,-7.7) 97(6.2,7.7) 98(5.8,7.7) 99(5.4,7.7) 100(5,7.7) 101(4.6,7.7) 102(4.2,7.7) 103(3.8,7.7) 104(3.4,7.7) 105(3,7.7) 106(2.6,7.7) 107(2.2,7.7) 108(1.8,7.7) 109(1.4,7.7) 110(1,7.7) 111(0.6,7.7) 112(0.2,7.7) 113(-0.2,7.7) 114(-0.6,7.7) 115(-1,7.7) 116(-1.4,7.7) 117(-1.8,7.7) 118(-2.2,7.7) 119(-2.6,7.7) 120(-3,7.7) 121(-3.4,7.7) 122(-3.8,7.7) 123(-4.2,7.7) 124(-4.6,7.7) 125(-5,7.7) 126(-5.4,7.7) 127(-5.8,7.7) 128(-6.2,7.7)
  silkscreen extent -7.7,-6.3 6.3,6.99, body extent -8,-8 8,8, height 1.07
PW0016A_L [mm] "TSOP, 16-Leads, Body 5x4.4mm, Pitch 0.65mm, IPC High Density"
  oval 1.2x0.4 smd: 1(-2.85,2.275) 2(-2.85,1.625) 3(-2.85,0.975) 4(-2.85,0.325) 5(-2.85,-0.325) 6(-2.85,-0.975) 7(-2.85,-1.625) 8(-2.85,-2.275) 9(2.85,-2.275) 10(2.85,-1.625) 11(2.85,-0.975) 12(2.85,-0.325) 13(2.85,0.325) 14(2.85,0.975) 15(2.85,1.625) 16(2.85,2.275)
  silkscreen extent -2,-2.55 1.85,2.55, body extent -3.21,-2.5 3.21,2.5, height 1
RGT0016A [mm] "QFN, 16-Leads, Body 3x3mm, Pitch 0.5mm, Thermal Pad 1.45x1.45mm, TI Recommended"
  rrect42% 0.6x0.24 smd: 1(-1.4,0.75) 2(-1.4,0.25) 3(-1.4,-0.25) 4(-1.4,-0.75) 9(1.4,-0.75) 10(1.4,-0.25) 11(1.4,0.25) 12(1.4,0.75)
  rrect42% 0.24x0.6 smd: 5(-0.75,-1.4) 6(-0.25,-1.4) 7(0.25,-1.4) 8(0.75,-1.4) 13(0.75,1.4) 14(0.25,1.4) 15(-0.25,1.4) 16(-0.75,1.4)
  rrect7% 1.34x1.34 on Top Paste: 17(0,0)
  rrect7% 1.45x1.45 smd paste-0.725: 17(0,0)
  silkscreen extent -1.72,-1.73 1.72,1.73, body extent -1.5,-1.5 1.5,1.5, height 1
RGY0020A [mm] "QFN, 20-Leads, Body 4.5x3.5mm, Pitch 0.5mm, Thermal Pad 3.05x2.05mm, TI Recommended"
  oval 0.24x0.6 smd: 1(-0.75,2.15) 10(-0.75,-2.15) 11(0.75,-2.15) 20(0.75,2.15)
  oval 0.6x0.24 smd: 2(-1.65,1.75) 3(-1.65,1.25) 4(-1.65,0.75) 5(-1.65,0.25) 6(-1.65,-0.25) 7(-1.65,-0.75) 8(-1.65,-1.25) 9(-1.65,-1.75) 12(1.65,-1.75) 13(1.65,-1.25) 14(1.65,-0.75) 15(1.65,-0.25) 16(1.65,0.25) 17(1.65,0.75) 18(1.65,1.25) 19(1.65,1.75)
  rect 2.05x3.05 smd paste-1.025: 21(0,0)
  silkscreen extent -1.97,-2.47 1.97,2.48, body extent -1.75,-2.25 1.75,2.25, height 1
RGZ0048B-MFG [mm]
  rrect42% 0.6x0.24 smd paste+0 mask+0: 1(-3.4,2.75) 2(-3.4,2.25) 3(-3.4,1.75) 4(-3.4,1.25) 5(-3.4,0.75) 6(-3.4,0.25) 7(-3.4,-0.25) 8(-3.4,-0.75) 9(-3.4,-1.25) 10(-3.4,-1.75) 11(-3.4,-2.25) 12(-3.4,-2.75) 25(3.4,-2.75) 26(3.4,-2.25) 27(3.4,-1.75) 28(3.4,-1.25) 29(3.4,-0.75) 30(3.4,-0.25) 31(3.4,0.25) 32(3.4,0.75) 33(3.4,1.25) 34(3.4,1.75) 35(3.4,2.25) 36(3.4,2.75)
  rrect42% 0.24x0.6 smd paste+0 mask+0: 13(-2.75,-3.4) 14(-2.25,-3.4) 15(-1.75,-3.4) 16(-1.25,-3.4) 17(-0.75,-3.4) 18(-0.25,-3.4) 19(0.25,-3.4) 20(0.75,-3.4) 21(1.25,-3.4) 22(1.75,-3.4) 23(2.25,-3.4) 24(2.75,-3.4) 37(2.75,3.4) 38(2.25,3.4) 39(1.75,3.4) 40(1.25,3.4) 41(0.75,3.4) 42(0.25,3.4) 43(-0.25,3.4) 44(-0.75,3.4) 45(-1.25,3.4) 46(-1.75,3.4) 47(-2.25,3.4) 48(-2.75,3.4)
  rrect2% 4.1x4.1 smd paste-1000 mask+0: 49(0,0)
  silkscreen extent -4.38,-3.57 3.57,3.57, body extent -3.5,-3.5 3.5,3.5, height 1.02
RPU0010A-MFG [mm]
  rrect50% 0.65x0.2 smd paste+0 mask+0: 1(-0.875,0.25) 3(-0.875,-0.75) 5(0.875,-0.25)
  rrect50% 1x0.2 smd paste+0 mask+0: 2(-0.7,-0.25) 4(0.7,-0.75) 6(0.7,0.25)
  rrect40% 0.25x0.55 smd paste+0 mask+0: 7(0.75,0.925) 8(0.25,0.925) 9(-0.25,0.925) 10(-0.75,0.925)
  silkscreen extent -1.97,-1.5 1,1.6, body extent -1.3,-1.15 1.3,1.3, height 0.25
RSE0010A [mm] "QFN, 10-Leads, Body 1.5x2mm, Pitch 0.5mm, TI Recommended"
  rect 0.55x0.2 smd: 1(-0.675,0.75) 2(-0.675,0.25) 3(-0.675,-0.25) 4(-0.675,-0.75) 6(0.675,-0.75) 7(0.675,-0.25) 8(0.675,0.25) 9(0.675,0.75)
  rect 0.3x0.6 smd: 5(0,-0.9) 10(0,0.9)
  silkscreen extent -1.07,-1.17 0.77,1.18, body extent -0.77,-1.02 0.78,1.03, height 0.61
RSV0016A [mm] "QFN, 16-Leads, Body 1.8x2.6mm, Pitch 0.4mm, TI Recommended"
  rect 0.7x0.2 smd: 1(-0.75,0.6)
  rect 0.6x0.2 smd: 2(-0.8,0.2) 3(-0.8,-0.2) 4(-0.8,-0.6) 9(0.8,-0.6) 10(0.8,-0.2) 11(0.8,0.2) 12(0.8,0.6)
  rect 0.2x0.6 smd: 5(-0.6,-1.2) 6(-0.2,-1.2) 7(0.2,-1.2) 8(0.6,-1.2) 13(0.6,1.2) 14(0.2,1.2) 15(-0.2,1.2) 16(-0.6,1.2)
  silkscreen extent -1.08,-1.33 1.08,1.45, body extent -0.92,-1.32 0.92,1.33, height 0.56
RUA0042A-MFG [mm]
  rrect40% 0.6x0.25 smd paste+0 mask+0: 1(-1.65,4) 2(-1.65,3.5) 3(-1.65,3) 4(-1.65,2.5) 5(-1.65,2) 6(-1.65,1.5) 7(-1.65,1) 8(-1.65,0.5) 9(-1.65,0) 10(-1.65,-0.5) 11(-1.65,-1) 12(-1.65,-1.5) 13(-1.65,-2) 14(-1.65,-2.5) 15(-1.65,-3) 16(-1.65,-3.5) 17(-1.65,-4) 22(1.65,-4) 23(1.65,-3.5) 24(1.65,-3) 25(1.65,-2.5) 26(1.65,-2) 27(1.65,-1.5) 28(1.65,-1) 29(1.65,-0.5) 30(1.65,0) 31(1.65,0.5) 32(1.65,1) 33(1.65,1.5) 34(1.65,2) 35(1.65,2.5) 36(1.65,3) 37(1.65,3.5) 38(1.65,4)
  rrect40% 0.25x0.6 smd paste+0 mask+0: 18(-0.75,-4.4) 19(-0.25,-4.4) 20(0.25,-4.4) 21(0.75,-4.4) 39(0.75,4.4) 40(0.25,4.4) 41(-0.25,4.4) 42(-0.75,4.4)
  rrect5% 2.05x7.55 smd paste-1000 mask+0: 43(0,0)
  silkscreen extent -2.65,-4.55 1.8,4.55, body extent -2.05,-4.8 2.05,4.8, height 0.25
RWB0012A [mm] "QFN, 12-Leads, Body 1.6x1.6mm, Pitch 0.4mm"
  rrect57% 0.7x0.2 smd paste-0.1: 1(-0.65,0.2) 2(-0.65,-0.2) 7(0.65,-0.2) 8(0.65,0.2)
  rrect57% 0.2x0.5 smd: 3(-0.6,-0.75) 4(-0.2,-0.75) 5(0.2,-0.75) 6(0.6,-0.75) 9(0.6,0.75) 10(0.2,0.75) 11(-0.2,0.75) 12(-0.6,0.75)
  silkscreen extent -0.92,-0.91 0.92,0.91, body extent -0.8,-0.8 0.8,0.8, height 0.4
SMB-Bi [mil] "Molded Diode, 2-Leads, Body 5.4x3.6mm, IPC Medium Density, based on OnSemi component dimensions"
  rect 85x107.99 smd: 1(-87.01,0) 2(87.01,0)
  silkscreen extent -125,-79 125,79, body extent -104,-73 104,73, height 89
SOIC-8 [mm] "duplicate of SO-8.  SOIC, 8-Leads, Body 5.0x4.0mm (max), Pitch 1.27mm, IPC Medium Density"
  rrect17% 1.45x0.6 smd: 1(-2.725,1.905) 2(-2.725,0.635) 3(-2.725,-0.635) 4(-2.725,-1.905) 5(2.725,-1.905) 6(2.725,-0.635) 7(2.725,0.635) 8(2.725,1.905)
  silkscreen extent -3.5,-2.5 0.9,2.5, body extent -3,-2.45 3,2.45, height 1.63
SOT-23 [mm] "SOT23, 3-Leads, Body 2.9x1.3mm, Pitch 0.95mm, Lead Span 2.5mm, IPC Medium Density"
  rrect50% 1x0.6 smd: 1(-1.2,0.95) 2(-1.2,-0.95) 3(1.2,0)
  silkscreen extent -1.63,-1.5 0.7,1.5, body extent -1.16,-1.45 1.21,1.45, height 1
SOT-323 [mm] "Diodes Inc recommended land pattern.  2016-02-24"
  rrect21% 0.6x0.47 smd: 1(-0.95,0.65) 2(-0.95,-0.65) 3(0.95,0)
  silkscreen extent -1.14,-1.22 0.77,1.22, body extent -1.13,-1.13 1.12,1.12, height 1.13
Sullins_PBC02SAAN [mm] "Sullins 100mil, 1x2, 230 mil above insulator"
  rect 1.65x1.65 hole 1.016: 1(0,1.27)
  round 1.65 hole 1.016: 2(0,-1.27)
  silkscreen extent -1.37,-2.54 1.27,3.1, body extent -1.27,-2.54 1.27,2.54, height 8.38
Sullins_PxC05SAAN [mm] "Header, 2.54mm, 5x1, TH"
  rect 1.55x1.55 hole 1.016: 1(-5.08,0)
  round 1.55 hole 1.016: 2(-2.54,0) 3(0,0) 4(2.54,0) 5(5.08,0)
  silkscreen extent -6.35,-1.75 6.35,1.27, body extent -6.35,-1.27 6.35,1.27, height 5.84
Sullins_xxPC005DAAN-RC [mm] "Header, 2.54mm, 5x2, TH"
  rrect50% 1.5x1.5 hole 1: 1(-1.27,5.08)
  round 1.5 hole 1: 2(1.27,5.08) 3(-1.27,2.54) 4(1.27,2.54) 5(-1.27,0) 6(1.27,0) 7(-1.27,-2.54) 8(1.27,-2.54) 9(-1.27,-5.08) 10(1.27,-5.08)
  body extent -2.5,-6.35 2.5,6.35, height 8.34
SW_CAS-120TA [mm] "COPAL ELECTRONICS"
  rect 1.6x1 smd: 1(-1.15,1.75) 2(1.15,0) 3(-1.15,-1.75)
  silkscreen extent -2,-2.85 1.4,2.93, body extent -1.4,-2.85 1.4,2.85, height 2.51
SW_CAS-D20TA [mm] "SMD, 6-Leads, Body 5.4x3.9mm, Pitch 1.75mm"
  rect 1.6x1 smd: 1(-1.85,1.75) 2(-1.85,0) 3(-1.85,-1.75) 4(1.85,1.75) 5(1.85,0) 6(1.85,-1.75)
  silkscreen extent -1.95,-2.7 1.95,2.9, body extent -2.1,-2.7 2.1,2.7, height 2.5
TI_Stacked_Overlay_Small [mil]
  silkscreen extent -418,-98 418,98
TP_25MIL-SMT [mil]
  round 25 smd mask-2.5: 1(0,0)
TP_SM_1MM [mm] "1mm Test Point, SMT"
  round 1 smd paste-0.5: 1(0,0)
WE-MAPI_4020 [mm] "SMD, 2-Leads, Body 4.1x4.1mm"
  rect 0.98x3.7 smd: 1(-1.185,0) 2(1.185,0)
  silkscreen extent -2.15,-2.15 2.15,2.15, body extent -2.15,-2.15 2.15,2.15, height 2.1
WEEE_Minimum [mil] "WEEElie bin"
  silkscreen extent -95,-172 99,104
WL-SMCW_GREEN [mm] "WURTH"
  rect 0.8x0.8 smd: 1(-0.8,0) 2(0.8,0)
  silkscreen extent -1.9,-0.8 1.2,0.8, body extent -0.85,-0.45 0.85,0.45, height 0.8
WL-SMCW_RED [mm] "WURTH"
  rect 0.8x0.8 smd: 1(-0.8,0) 2(0.8,0)
  silkscreen extent -1.9,-0.8 1.2,0.8, body extent -0.85,-0.45 0.85,0.45, height 0.8
Wurth_60900213421 [mil] "Shunt, 2.54mm, Black"
  round 1 on Mech3: 0(0,0)
  body extent -98,-48 98,48, height 338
